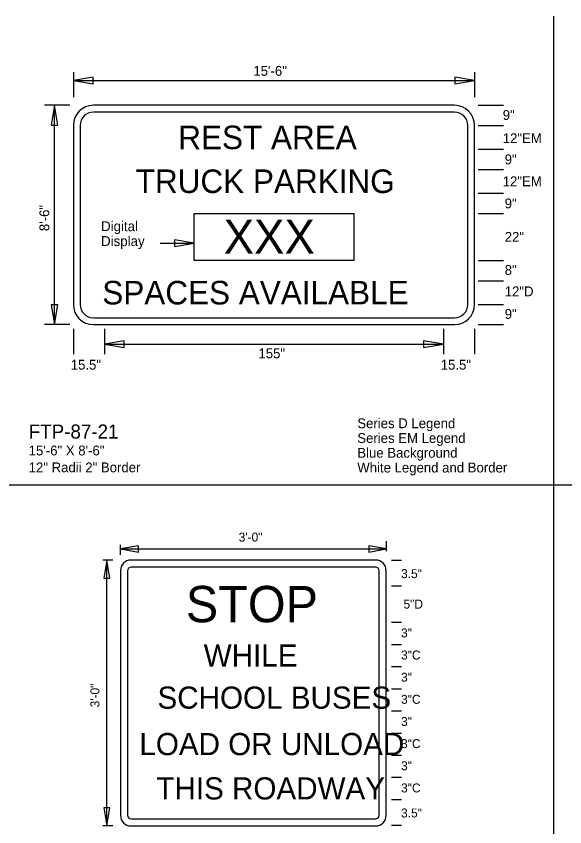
# Model space of a CAD drawing. Extents: x 0 to 770, y 0 to 495.
# Drawn here: x 388.1 to 581.3, y 209.6 to 495 of the extents above; entities that cross this region are included whole.
import ezdxf

# ---------------------------------------------------------------- set-up
doc = ezdxf.new("R2010")
doc.units = 0
for name, color, linetype in [('Default', 7, 'Continuous'), ('Dimension', 7, 'Continuous'), ('GSBWFill', 7, 'Continuous'), ('GSDims', 7, 'Continuous'), ('SheetLines_dp', 7, 'Continuous'), ('TextStructures', 7, 'Continuous')]:
    doc.layers.add(name, color=color, linetype=linetype)

msp = doc.modelspace()

# ---------------------------------------------------------------- linework, layer by layer
at = {"layer": 'Default'}
for p, q in [((542.46, 463.63), (415.29, 463.63)), ((542.46, 461.24), (415.29, 461.24)), ((408.22, 456.57), (408.22, 393.45)), ((410.61, 456.57), (410.61, 393.45)), ((547.13, 393.45), (547.13, 456.57)), ((549.52, 393.45), (549.52, 456.57)), ((415.29, 388.78), (542.46, 388.78)), ((415.29, 386.39), (542.46, 386.39))]:
    msp.add_line(p, q, dxfattribs=at)
msp.add_lwpolyline([(450.78, 425.58), (506.96, 425.58), (506.96, 408.99), (450.78, 408.99)], close=True, dxfattribs=at)
for centre, radius, start, end in [((415.29, 456.57), 7.06, 90, 180), ((542.46, 456.57), 7.06, 0, 90), ((415.29, 456.57), 4.67, 90, 180), ((542.46, 456.57), 4.67, 0, 90), ((415.29, 393.45), 7.06, 180, 270), ((415.29, 393.45), 4.67, 180, 270), ((542.46, 393.45), 7.06, 270, 0), ((542.46, 393.45), 4.67, 270, 0)]:
    msp.add_arc(centre, radius, start, end, dxfattribs=at)
at = {"layer": 'Dimension'}
for points in [[(408.22, 472.4), (415.17, 471.22), (415.17, 473.58)], [(549.52, 472.4), (542.57, 473.58), (542.57, 471.22)], [(401.62, 463.63), (400.44, 456.69), (402.79, 456.69)], [(450.78, 415.07), (443.83, 416.24), (443.83, 413.89)], [(401.62, 386.39), (402.79, 393.34), (400.44, 393.34)], [(419.2, 379.55), (426.15, 378.38), (426.15, 380.73)], [(538.54, 379.55), (531.6, 380.73), (531.6, 378.38)], [(424.82, 307.4), (431.14, 306.33), (431.14, 308.47)], [(518.58, 307.4), (512.27, 308.47), (512.27, 306.33)], [(420.04, 303.48), (418.97, 297.17), (421.11, 297.17)], [(420.04, 209.89), (421.11, 216.2), (418.97, 216.2)]]:
    msp.add_lwpolyline(points, close=True, dxfattribs=at)
at = {"layer": 'GSBWFill'}
for p, q in [((514.68, 303.48), (428.56, 303.48)), ((424.82, 299.74), (424.82, 213.62)), ((427.32, 299.74), (427.32, 213.62)), ((514.68, 300.99), (428.56, 300.99)), ((515.93, 213.62), (515.93, 299.74)), ((518.42, 213.62), (518.42, 299.74)), ((428.56, 212.38), (514.68, 212.38)), ((428.56, 209.89), (514.68, 209.89))]:
    msp.add_line(p, q, dxfattribs=at)
for centre, radius, start, end in [((428.56, 299.74), 3.74, 90, 180), ((514.68, 299.74), 3.74, 0, 90), ((428.56, 299.74), 1.25, 90, 180), ((514.68, 299.74), 1.25, 0, 90), ((428.56, 213.62), 3.74, 180, 270), ((428.56, 213.62), 1.25, 180, 270), ((514.68, 213.62), 3.74, 270, 0), ((514.68, 213.62), 1.25, 270, 0)]:
    msp.add_arc(centre, radius, start, end, dxfattribs=at)
at = {"layer": 'GSDims'}
for p, q in [((408.22, 475.34), (408.22, 466.48)), ((549.52, 475.34), (549.52, 466.48)), ((408.22, 472.4), (549.52, 472.4)), ((406.94, 463.63), (398.07, 463.63)), ((401.62, 386.39), (401.62, 463.63)), ((550.86, 463.63), (559.73, 463.63)), ((550.86, 456.48), (559.73, 456.48)), ((550.86, 448.18), (559.73, 448.18)), ((550.86, 441.03), (559.73, 441.03)), ((550.86, 432.74), (559.73, 432.74)), ((550.86, 425.58), (559.73, 425.58)), ((438.77, 415.07), (450.78, 415.07)), ((550.86, 408.99), (559.73, 408.99)), ((550.86, 401.84), (559.73, 401.84)), ((550.86, 393.54), (559.73, 393.54)), ((406.94, 386.39), (398.07, 386.39)), ((550.86, 386.39), (559.73, 386.39)), ((408.22, 384.87), (408.22, 376.01)), ((419.2, 384.87), (419.2, 376.01)), ((538.54, 384.87), (538.54, 376.01)), ((549.52, 384.87), (549.52, 376.01)), ((419.2, 379.55), (538.54, 379.55)), ((424.82, 305.29), (424.82, 308.81)), ((518.58, 306.59), (518.58, 310.11)), ((424.82, 307.4), (518.58, 307.4)), ((422.15, 303.48), (418.63, 303.48)), ((420.04, 210.1), (420.04, 303.48)), ((520.32, 303.48), (523.84, 303.48)), ((520.32, 294.38), (523.84, 294.38)), ((520.32, 281.6), (523.84, 281.6)), ((520.32, 273.8), (523.84, 273.8)), ((520.32, 266), (523.84, 266)), ((520.32, 258.2), (523.84, 258.2)), ((520.32, 250.4), (523.84, 250.4)), ((520.32, 242.6), (523.84, 242.6)), ((520.32, 234.8), (523.84, 234.8)), ((520.32, 227), (523.84, 227)), ((520.32, 227), (523.84, 227)), ((520.32, 219.2), (523.84, 219.2)), ((422.15, 209.89), (418.63, 209.89)), ((520.32, 210.1), (523.84, 210.1))]:
    msp.add_line(p, q, dxfattribs=at)
at = {"layer": 'SheetLines_dp'}
for p, q in [((577.5, 0), (577.5, 495)), ((0, 330), (770, 330))]:
    msp.add_line(p, q, dxfattribs=at)

# ---------------------------------------------------------------- texts
at = {"layer": 'Default'}
for s, height, p in [('REST AREA', 8.294, (445.17, 448.18)), ('TRUCK PARKING', 8.2939, (430.2, 432.74)), ('XXX', 12.007, (461.16, 411.35)), ('SPACES AVAILABLE', 8.2939, (418.42, 393.51)), ('STOP', 12.785, (447.84, 281.6)), ('WHILE', 7.8, (454.14, 266)), ('SCHOOL BUSES', 7.7998, (437.86, 251.16)), ('LOAD OR UNLOAD', 7.7998, (431.48, 234.8)), ('THIS ROADWAY', 7.7998, (437.45, 219.2))]:
    msp.add_text(s, height=height, dxfattribs=at).set_placement(p)
at = {"layer": 'Dimension'}
for s, p in [('Digital', (417.99, 419.31)), ('Display', (417.99, 414.06))]:
    msp.add_text(s, height=3.5, dxfattribs=at).set_placement(p)
at = {"layer": 'TextStructures'}
for s, height, p in [('15\'-6"', 3.465, (471.63, 474.01)), ('9"', 3.465, (559.46, 458.49)), ('12"EM', 3.465, (559.46, 450.3)), ('9"', 3.465, (560.17, 442.87)), ('12"EM', 3.465, (559.46, 435.13)), ('9"', 3.465, (560.17, 427.34)), ('22"', 3.465, (560.17, 415.57)), ('8"', 3.465, (560.17, 403.91)), ('12"D', 3.465, (560.17, 396.38)), ('9"', 3.465, (560.17, 388.43)), ('155"', 3.465, (473.43, 374.56)), ('15.5"', 3.465, (407.31, 370.54)), ('15.5"', 3.465, (537.63, 370.54)), ('FTP-87-21', 4.95, (392.49, 346.28)), ('Series D Legend', 3.465, (508.24, 349.93)), ('Series EM Legend', 3.465, (508.24, 344.73)), ('15\'-6" X 8\'-6"', 3.465, (392.49, 340.34)), ('Blue Background', 3.465, (508.24, 339.54)), ('12" Radii 2" Border   ', 3.465, (392.49, 334.4)), ('White Legend and Border  ', 3.465, (508.24, 334.34)), ('3\'-0"', 3.15, (466.45, 310)), ('3.5"', 3.15, (523.65, 297.14)), ('5"D', 3.15, (524.51, 286.41)), ('3"', 3.15, (523.65, 276.28)), ('3"C', 3.15, (523.65, 268.48)), ('3"', 3.15, (523.65, 260.68)), ('3"C', 3.15, (523.65, 252.88)), ('3"', 3.15, (523.65, 245.08)), ('3"C', 3.15, (523.65, 237.28)), ('3"', 3.15, (523.65, 229.48)), ('3"C', 3.15, (523.65, 221.68)), ('3.5"', 3.15, (523.65, 212.86))]:
    msp.add_text(s, height=height, dxfattribs=at).set_placement(p)
for s, height, p in [('8\'-6"', 3.465, (399.75, 419.32)), ('3\'-0"', 3.15, (417.4, 251.62))]:
    msp.add_text(s, height=height, rotation=90, dxfattribs=at).set_placement(p)

doc.saveas('drawing.dxf')
